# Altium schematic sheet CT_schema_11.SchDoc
size 146 x 119 mm
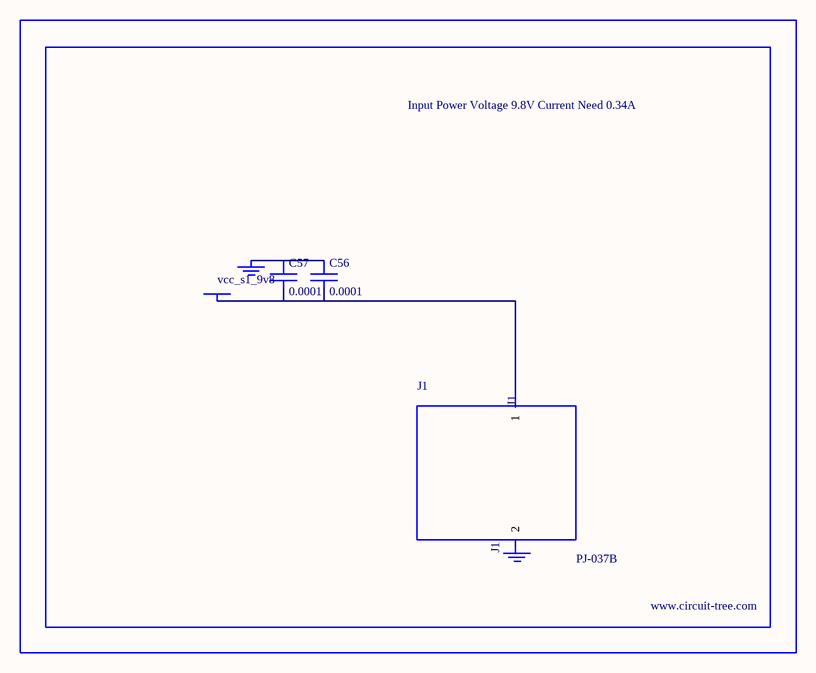
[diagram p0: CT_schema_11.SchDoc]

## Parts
BORDER10  (no value)
C56  0.0001  [EXV-9H]
C57  0.0001  [EXV-9H]
GND_INSTANCE_10_0  (no value)
GND_INSTANCE_10_1  (no value)
J1  PJ-037B  [PJ-037B_PACKAGE]
POWER_INSTANCE_10_0  vcc_s1_9v8

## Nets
NetC56_1: C56.1 C57.1 GND_INSTANCE_10_0.0(GND)
NetC56_2: C56.2 C57.2 J1.1 POWER_INSTANCE_10_0.0(PWR)

Not connected (* = marked no-connect by the designer): GND_INSTANCE_10_1 0(GND); J1 2

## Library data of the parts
BORDER10 = BORDER_PAGE10
C56 C57 = EDK107M035A9HAA
GND_INSTANCE_10_0 GND_INSTANCE_10_1 = GND
POWER_INSTANCE_10_0 = PWR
